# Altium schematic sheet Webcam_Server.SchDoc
size A
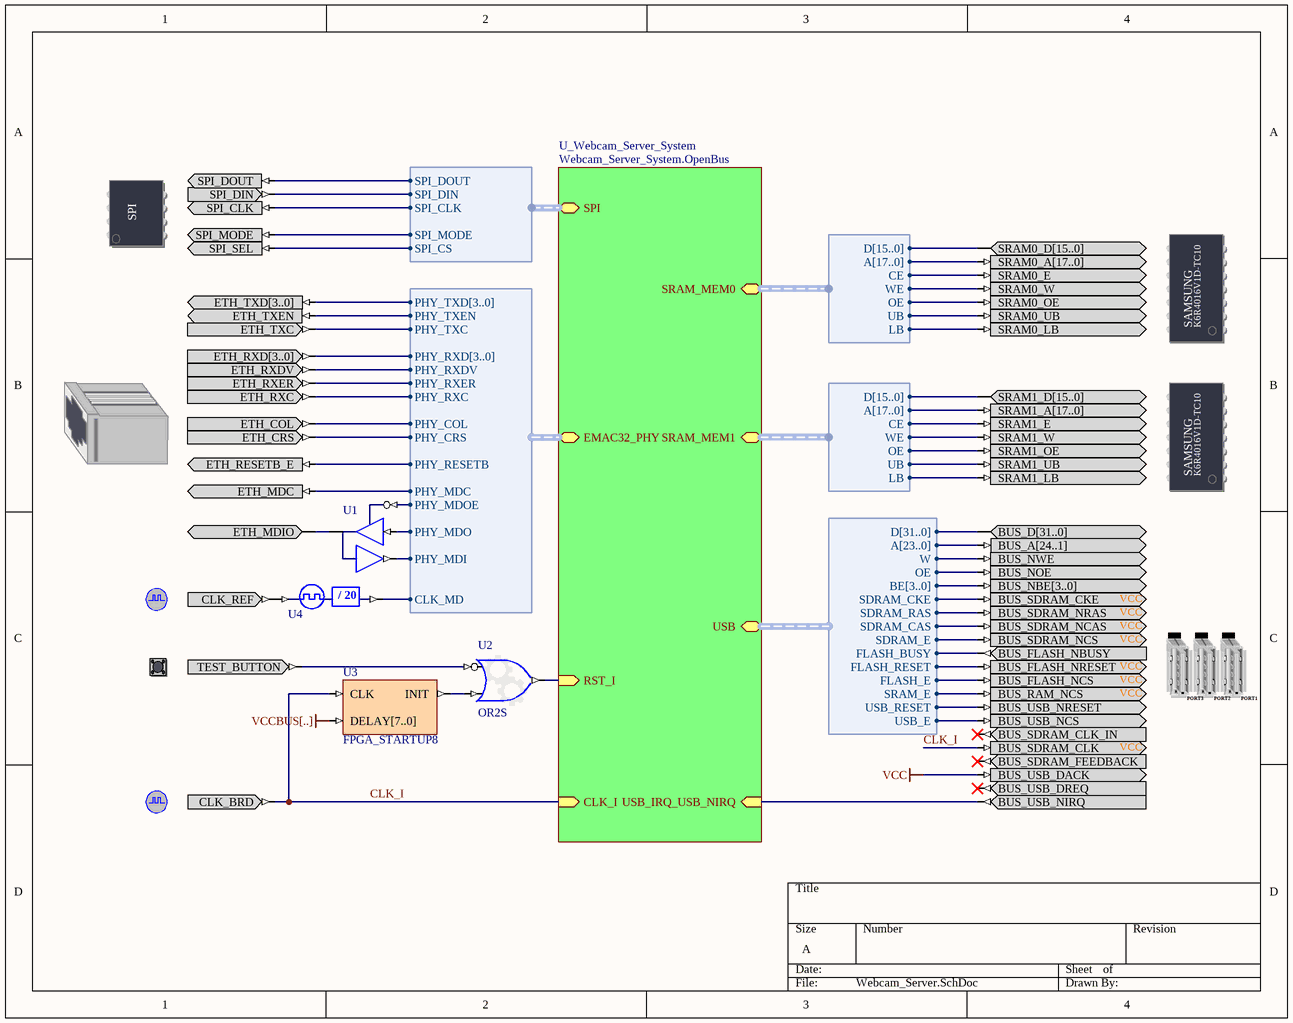
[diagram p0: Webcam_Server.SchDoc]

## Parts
(Parts that share a designator on the sheet are numbered #1, #2 ... from top to bottom, then left to right.)
?#1  SERIALFMEMORY  (value not drawn)
?#2  SRAM_DAUGHTER0  (value not drawn)
?#3  ETH_PHY  (value not drawn)
?#4  SRAM_DAUGHTER1  (value not drawn)
?#5  SHARED_USB  (value not drawn)
?#6  CLOCK_REFERENCE  (value not drawn)
?#7  TEST_BUTTON  (value not drawn)
?#8  CLOCK_BOARD  (value not drawn)
U1  IOBUF  (value not drawn)
U2  OR2S
U3  FPGA_STARTUP8
U4  CDIV20DC50  (value not drawn)

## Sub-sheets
U_Webcam_Server_System = Webcam_Server_System.OpenBus: EMAC32_PHY (harness EMAC32), SRAM_MEM0 (harness WB_MEM_CTRL_SRAM16_A18), SRAM_MEM1 (harness WB_MEM_CTRL_SRAM16_A18), RST_I (in), CLK_I (in), USB_IRQ_USB_NIRQ (in), USB (harness WB_SHARED_MEM_CTRL), SPI (harness SPI_W_NB)

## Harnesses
WB_MEM_CTRL_SRAM16_A18: D[15..0], A[17..0], CE, WE, OE, UB, LB
EMAC32: PHY_TXD[3..0], PHY_TXEN, PHY_TXC, PHY_RXD[3..0], PHY_RXDV, PHY_RXER, PHY_RXC, PHY_COL, PHY_CRS, PHY_RESETB, PHY_MDC, PHY_MDOE, PHY_MDO, PHY_MDI, CLK_MD
WB_SHARED_MEM_CTRL: D[31..0], A[23..0], W, OE, BE[3..0], SDRAM_CKE, SDRAM_RAS, SDRAM_CAS, SDRAM_E, FLASH_BUSY, FLASH_RESET, FLASH_E, SRAM_E, USB_RESET, USB_E
SPI_W_NB: SPI_DOUT, SPI_DIN, SPI_CLK, SPI_CS, SPI_MODE

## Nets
VCC: ?#5.BUS_USB_DACK
VCCBUS[..]: U3.DELAY[7..0]
CLK_I: ?#5.BUS_SDRAM_CLK ?#8.CLK_BRD U3.CLK ; sheet U_Webcam_Server_System/CLK_I
Net?#1_SPI_CLK: ?#1.SPI_CLK ; sheet U_Webcam_Server_System/SPI.SPI_CLK
Net?#1_SPI_DIN: ?#1.SPI_DIN ; sheet U_Webcam_Server_System/SPI.SPI_DIN
Net?#1_SPI_DOUT: ?#1.SPI_DOUT ; sheet U_Webcam_Server_System/SPI.SPI_DOUT
Net?#1_SPI_MODE: ?#1.SPI_MODE ; sheet U_Webcam_Server_System/SPI.SPI_MODE
Net?#1_SPI_SEL: ?#1.SPI_SEL ; sheet U_Webcam_Server_System/SPI.SPI_CS
Net?#2_SRAM0_E: ?#2.SRAM0_E ; sheet U_Webcam_Server_System/SRAM_MEM0.CE
Net?#2_SRAM0_LB: ?#2.SRAM0_LB ; sheet U_Webcam_Server_System/SRAM_MEM0.LB
Net?#2_SRAM0_OE: ?#2.SRAM0_OE ; sheet U_Webcam_Server_System/SRAM_MEM0.OE
Net?#2_SRAM0_UB: ?#2.SRAM0_UB ; sheet U_Webcam_Server_System/SRAM_MEM0.UB
Net?#2_SRAM0_W: ?#2.SRAM0_W ; sheet U_Webcam_Server_System/SRAM_MEM0.WE
Net?#3_ETH_COL: ?#3.ETH_COL ; sheet U_Webcam_Server_System/EMAC32_PHY.PHY_COL
Net?#3_ETH_CRS: ?#3.ETH_CRS ; sheet U_Webcam_Server_System/EMAC32_PHY.PHY_CRS
Net?#3_ETH_MDC: ?#3.ETH_MDC ; sheet U_Webcam_Server_System/EMAC32_PHY.PHY_MDC
Net?#3_ETH_MDIO: ?#3.ETH_MDIO U1.IO
Net?#3_ETH_RESETB_E: ?#3.ETH_RESETB_E ; sheet U_Webcam_Server_System/EMAC32_PHY.PHY_RESETB
Net?#3_ETH_RXC: ?#3.ETH_RXC ; sheet U_Webcam_Server_System/EMAC32_PHY.PHY_RXC
Net?#3_ETH_RXDV: ?#3.ETH_RXDV ; sheet U_Webcam_Server_System/EMAC32_PHY.PHY_RXDV
Net?#3_ETH_RXER: ?#3.ETH_RXER ; sheet U_Webcam_Server_System/EMAC32_PHY.PHY_RXER
Net?#3_ETH_TXC: ?#3.ETH_TXC ; sheet U_Webcam_Server_System/EMAC32_PHY.PHY_TXC
Net?#3_ETH_TXEN: ?#3.ETH_TXEN ; sheet U_Webcam_Server_System/EMAC32_PHY.PHY_TXEN
Net?#4_SRAM1_E: ?#4.SRAM1_E ; sheet U_Webcam_Server_System/SRAM_MEM1.CE
Net?#4_SRAM1_LB: ?#4.SRAM1_LB ; sheet U_Webcam_Server_System/SRAM_MEM1.LB
Net?#4_SRAM1_OE: ?#4.SRAM1_OE ; sheet U_Webcam_Server_System/SRAM_MEM1.OE
Net?#4_SRAM1_UB: ?#4.SRAM1_UB ; sheet U_Webcam_Server_System/SRAM_MEM1.UB
Net?#4_SRAM1_W: ?#4.SRAM1_W ; sheet U_Webcam_Server_System/SRAM_MEM1.WE
Net?#5_BUS_FLASH_NBUSY: ?#5.BUS_FLASH_NBUSY ; sheet U_Webcam_Server_System/USB.FLASH_BUSY
Net?#5_BUS_FLASH_NCS: ?#5.BUS_FLASH_NCS ; sheet U_Webcam_Server_System/USB.FLASH_E
Net?#5_BUS_FLASH_NRESET: ?#5.BUS_FLASH_NRESET ; sheet U_Webcam_Server_System/USB.FLASH_RESET
Net?#5_BUS_NOE: ?#5.BUS_NOE ; sheet U_Webcam_Server_System/USB.OE
Net?#5_BUS_NWE: ?#5.BUS_NWE ; sheet U_Webcam_Server_System/USB.W
Net?#5_BUS_RAM_NCS: ?#5.BUS_RAM_NCS ; sheet U_Webcam_Server_System/USB.SRAM_E
Net?#5_BUS_SDRAM_CKE: ?#5.BUS_SDRAM_CKE ; sheet U_Webcam_Server_System/USB.SDRAM_CKE
Net?#5_BUS_SDRAM_NCAS: ?#5.BUS_SDRAM_NCAS ; sheet U_Webcam_Server_System/USB.SDRAM_CAS
Net?#5_BUS_SDRAM_NCS: ?#5.BUS_SDRAM_NCS ; sheet U_Webcam_Server_System/USB.SDRAM_E
Net?#5_BUS_SDRAM_NRAS: ?#5.BUS_SDRAM_NRAS ; sheet U_Webcam_Server_System/USB.SDRAM_RAS
Net?#5_BUS_USB_NCS: ?#5.BUS_USB_NCS ; sheet U_Webcam_Server_System/USB.USB_E
Net?#5_BUS_USB_NIRQ: ?#5.BUS_USB_NIRQ ; sheet U_Webcam_Server_System/USB_IRQ_USB_NIRQ
Net?#5_BUS_USB_NRESET: ?#5.BUS_USB_NRESET ; sheet U_Webcam_Server_System/USB.USB_RESET
Net?#6_CLK_REF: ?#6.CLK_REF U4.CLKIN
Net?#7_TEST_BUTTON: ?#7.TEST_BUTTON U2.I0
NetU1_I: U1.I ; sheet U_Webcam_Server_System/EMAC32_PHY.PHY_MDO
NetU1_O: U1.O ; sheet U_Webcam_Server_System/EMAC32_PHY.PHY_MDI
NetU1_T: U1.T ; sheet U_Webcam_Server_System/EMAC32_PHY.PHY_MDOE
NetU2_I1: U2.I1 U3.INIT
NetU2_O: U2.O ; sheet U_Webcam_Server_System/RST_I
NetU4_CLKDV: U4.CLKDV ; sheet U_Webcam_Server_System/EMAC32_PHY.CLK_MD

Not connected (* = marked no-connect by the designer): ?#2 SRAM0_A[17..0] SRAM0_D[15..0]; ?#3 ETH_RXD[3..0] ETH_TXD[3..0]; ?#4 SRAM1_A[17..0] SRAM1_D[15..0]; ?#5 BUS_A[24..1] BUS_D[31..0] BUS_NBE[3..0] BUS_SDRAM_CLK_IN* BUS_SDRAM_FEEDBACK* BUS_USB_DREQ*

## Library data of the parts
?#1 = SPI_BUS: Serial SPI Flash RAM; PortComponent: True
?#2 = SRAM_DAUGHTER0: Free Static RAM - Daughterboard; PortComponent: True
?#3 = ETH_PHY: Ethernet PHY-interface; PortComponent: True
?#4 = SRAM_DAUGHTER1: Free Static RAM - Daughterboard; PortComponent: True
?#5 = SHARED_USB: Common-Bus USB; PortComponent: True
?#6 = CLOCK_REFERENCE: Global System Clock Reference Supply; PortComponent: True
?#7 = TEST_BUTTON: Test / Reset Button; PortComponent: True
?#8 = CLOCK_BOARD: Global System Clock Supply; PortComponent: True
U1 = iobuf: Input/Output Buffer; Enable: Low; Control: Common Control T; ArchiveName: GENERIC; VHDLIB_SIM: GENERIC_LIB
U2 = GATE: Configurable Generic Gate; ConfiguratorName: GENERIC_GATE; ConfigurationParameters: {}Version[1.0]{}GateKind[OR]{}BusInput[False]{}GateInputType[Bit]{}GateOutputOption[Normal]{}BusWidth[8]{}RegisterOutputs[False]{}NegativeClockEdge[False]{}InputCount[2]{}InputInvert0[True]{}InputInvert1[False]{}
U3 = FPGA_STARTUP8: FPGA Startup With 8 Bit Delay
U4 = CDIV20DC50: Clock Divider by 20 with 50% Duty Cycle Output; DivisorRate: 20; DutyCycle: 50; ArchiveName: GENERIC; VHDLIB_SIM: GENERIC_LIB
